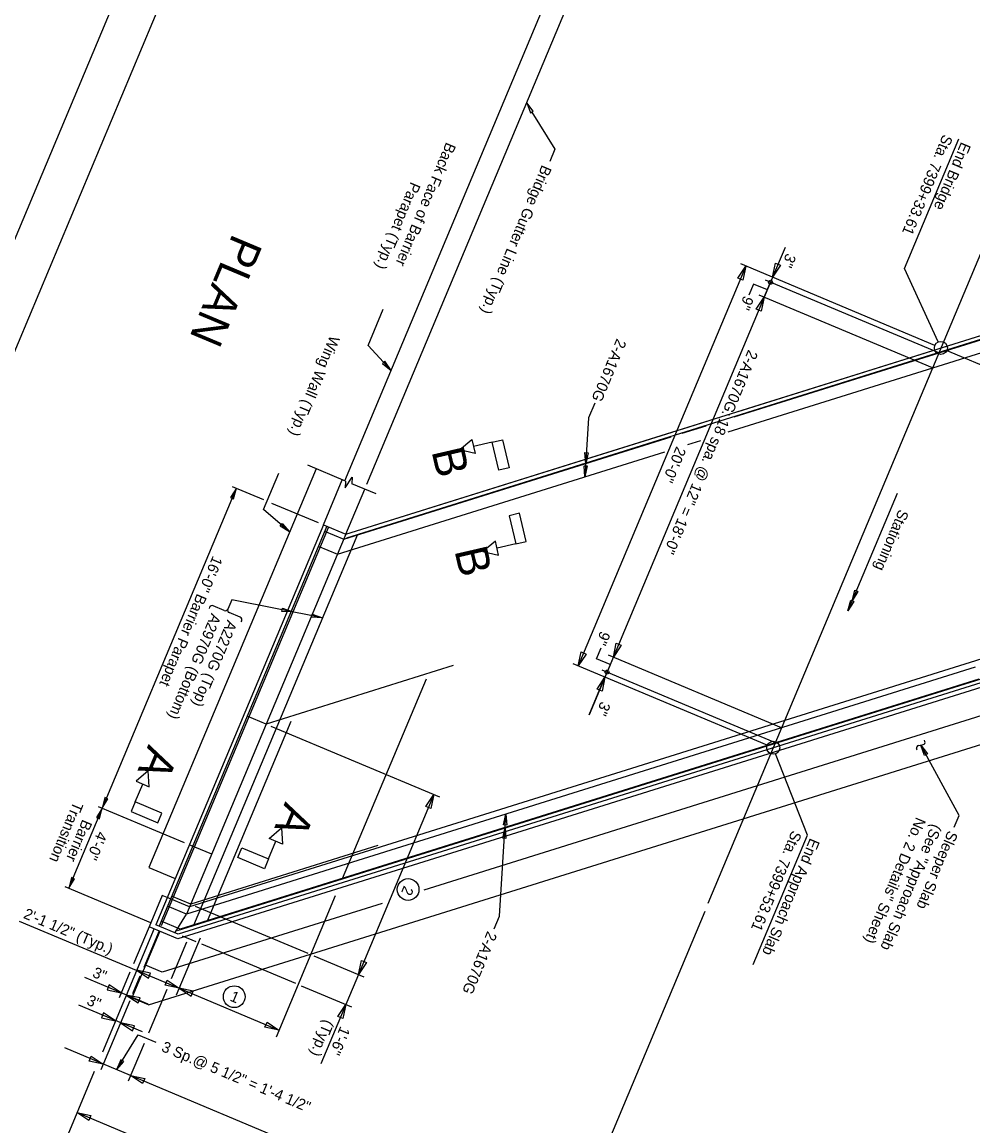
# Model space of a CAD drawing. Extents: x 1968564 to 1968701, y 796599 to 796766.
# Drawn here: x 1968596.6 to 1968640.5, y 796669.3 to 796720.2 of the extents above; entities that cross this region are included whole.
import ezdxf

# ---------------------------------------------------------------- set-up
doc = ezdxf.new("R2010")
doc.units = 0
for name, color, linetype in [('BR_AUTO DIMENSION', 7, 'Continuous'), ('BR_BORDER LINES', 7, 'Continuous'), ('BR_CENTER LINES', 7, 'Continuous'), ('BR_CONCRETE', 7, 'Continuous'), ('BR_DETAILS', 7, 'Continuous'), ('BR_REBAR', 7, 'Continuous'), ('BR_TABLE LINES', 7, 'Continuous'), ('BR_TEXT', 7, 'Continuous'), ('Level 31', 7, 'Continuous')]:
    doc.layers.add(name, color=color, linetype=linetype)

msp = doc.modelspace()

# ---------------------------------------------------------------- linework, layer by layer
at = {"layer": 'BR_AUTO DIMENSION'}
for p, q in [((1968611.464, 796699.011), (1968632.524, 796749.225)), ((1968612.483, 796698.855), (1968633.446, 796748.838)), ((1968612.483, 796698.855), (1968632.89, 796747.51)), ((1968620.099, 796716.016), (1968621.16, 796714.305)), ((1968637.292, 796708.802), (1968639.798, 796714.777)), ((1968621.16, 796714.305), (1968620.923, 796713.741)), ((1968631.786, 796709.774), (1968631.208, 796708.395)), ((1968629.977, 796708.911), (1968622.241, 796690.467)), ((1968638.698, 796705.253), (1968629.746, 796709.008)), ((1968631.388, 796708.825), (1968631.079, 796708.087)), ((1968638.849, 796705.41), (1968637.292, 796708.802)), ((1968630.332, 796708.083), (1968630.116, 796707.569)), ((1968630.965, 796707.817), (1968630.332, 796708.083)), ((1968630.821, 796707.472), (1968631.079, 796708.087)), ((1968631.079, 796708.087), (1968630.821, 796707.472)), ((1968638.877, 796704.907), (1968630.881, 796708.261)), ((1968630.821, 796707.472), (1968622.744, 796688.214)), ((1968638.587, 796704.215), (1968630.59, 796707.569)), ((1968612.539, 796705.251), (1968613.243, 796706.93)), ((1968613.598, 796704.1), (1968612.539, 796705.251)), ((1968639.251, 796705.021), (1968648.6, 796701.1)), ((1968622.999, 796702.586), (1968622.715, 796701.91)), ((1968622.715, 796701.91), (1968622.55, 796699.196)), ((1968607.713, 796697.682), (1968608.417, 796699.36)), ((1968598.724, 796680.219), (1968606.46, 796698.663)), ((1968606.273, 796698.741), (1968607.709, 796698.139)), ((1968636.954, 796698.42), (1968634.687, 796693.016)), ((1968608.917, 796696.657), (1968607.713, 796697.682)), ((1968608.089, 796697.98), (1968610.238, 796697.078)), ((1968605.224, 796693.172), (1968605.202, 796693.12)), ((1968605.9, 796693.024), (1968605.387, 796693.239)), ((1968606.245, 796693.525), (1968606.063, 796693.091)), ((1968610.439, 796692.689), (1968606.245, 796693.525)), ((1968606.642, 796692.713), (1968606.13, 796692.928)), ((1968606.687, 796692.497), (1968606.709, 796692.549)), ((1968623.081, 796690.795), (1968623.296, 796691.308)), ((1968624.009, 796691.231), (1968623.601, 796690.258)), ((1968630.962, 796686.81), (1968622.011, 796690.564)), ((1968623.715, 796690.529), (1968623.081, 796690.795)), ((1968631.625, 796687.616), (1968623.629, 796690.97)), ((1968623.292, 796689.521), (1968623.601, 796690.258)), ((1968631.335, 796686.924), (1968623.338, 796690.278)), ((1968622.744, 796688.214), (1968623.472, 796689.951)), ((1968608.048, 796687.695), (1968615.831, 796684.431)), ((1968632.824, 796682.67), (1968631.349, 796686.415)), ((1968639.812, 796683.57), (1968638.053, 796686.82)), ((1968615.575, 796684.538), (1968612.094, 796676.239)), ((1968600.085, 796683.986), (1968604.049, 796682.324)), ((1968618.61, 796678.928), (1968618.897, 796683.633)), ((1968639.584, 796683.028), (1968639.812, 796683.57)), ((1968630.318, 796676.695), (1968632.824, 796682.67)), ((1968598.538, 796680.298), (1968602.502, 796678.635)), ((1968611.027, 796679.872), (1968608.292, 796673.35)), ((1968604.567, 796679.395), (1968609.763, 796677.216)), ((1968618.363, 796678.339), (1968618.61, 796678.928)), ((1968628.075, 796679.15), (1968621.849, 796664.307)), ((1968596.437, 796678.704), (1968603.817, 796675.609)), ((1968602.663, 796678.352), (1968600.277, 796672.663)), ((1968602.429, 796678.44), (1968601.71, 796676.726)), ((1968602.894, 796678.255), (1968602.184, 796676.562)), ((1968604.786, 796677.919), (1968603.681, 796675.284)), ((1968603.964, 796678.022), (1968604.583, 796677.762)), ((1968604.162, 796677.723), (1968603.457, 796676.043)), ((1968604.849, 796677.651), (1968609.183, 796675.833)), ((1968610.036, 796677.102), (1968612.35, 796676.131)), ((1968601.55, 796676.344), (1968601.054, 796675.161)), ((1968612.094, 796676.239), (1968610.366, 796672.119)), ((1968602.393, 796674.866), (1968599.461, 796676.096)), ((1968602.013, 796676.155), (1968601.671, 796675.34)), ((1968609.456, 796675.718), (1968611.77, 796674.748)), ((1968603.252, 796675.553), (1968602.403, 796673.529)), ((1968603.817, 796675.609), (1968608.428, 796673.675)), ((1968602.127, 796673.586), (1968599.195, 796674.816)), ((1968601.54, 796675.028), (1968600.205, 796671.843)), ((1968600.933, 796671.845), (1968601.931, 796673.452)), ((1968601.931, 796673.452), (1968602.74, 796673.113)), ((1968601.582, 796671.573), (1968598.541, 796672.848)), ((1968602.205, 796673.058), (1968601.473, 796671.311)), ((1968599.902, 796671.768), (1968598.173, 796667.646)), ((1968654.146, 796649.526), (1968601.582, 796671.573)), ((1968620.43, 796660.923), (1968599.105, 796669.867))]:
    msp.add_line(p, q, dxfattribs=at)
for points in [[(1968620.165, 796716.053), (1968619.861, 796716.446), (1968620.036, 796715.981)], [(1968629.61, 796708.36), (1968629.977, 796708.911), (1968629.841, 796708.263)], [(1968631.574, 796708.946), (1968631.208, 796708.395), (1968631.344, 796709.042)], [(1968630.454, 796706.921), (1968630.821, 796707.472), (1968630.685, 796706.825)], [(1968613.204, 796704.417), (1968613.598, 796704.1), (1968613.315, 796704.519)], [(1968622.693, 796700.303), (1968622.587, 796699.809), (1968622.543, 796700.312)], [(1968622.655, 796699.691), (1968622.55, 796699.196), (1968622.506, 796699.7)], [(1968606.335, 796698.173), (1968606.46, 796698.663), (1968606.197, 796698.231)], [(1968608.577, 796697.031), (1968608.917, 796696.657), (1968608.483, 796696.914)], [(1968635.143, 796693.908), (1968634.88, 796693.476), (1968635.005, 796693.966)], [(1968608.587, 796693.134), (1968609.063, 796692.963), (1968608.558, 796692.987)], [(1968634.95, 796693.448), (1968634.687, 796693.016), (1968634.812, 796693.506)], [(1968609.963, 796692.86), (1968610.439, 796692.689), (1968609.934, 796692.713)], [(1968624.226, 796691.424), (1968623.859, 796690.873), (1968623.995, 796691.521)], [(1968622.608, 796691.018), (1968622.241, 796690.467), (1968622.377, 796691.115)], [(1968623.106, 796689.4), (1968623.472, 796689.951), (1968623.336, 796689.303)], [(1968638.225, 796686.345), (1968638.053, 796686.82), (1968638.357, 796686.416)], [(1968600.395, 796684.398), (1968600.271, 796683.908), (1968600.534, 796684.34)], [(1968615.208, 796683.987), (1968615.575, 796684.538), (1968615.439, 796683.89)], [(1968600.147, 796683.418), (1968600.271, 796683.908), (1968600.009, 796683.476)], [(1968618.792, 796683.138), (1968618.897, 796683.633), (1968618.941, 796683.129)], [(1968618.754, 796682.525), (1968618.86, 796683.02), (1968618.904, 796682.516)], [(1968598.848, 796680.71), (1968598.724, 796680.219), (1968598.987, 796680.652)], [(1968612.46, 796676.79), (1968612.094, 796676.239), (1968612.23, 796676.886)], [(1968602.505, 796676.294), (1968601.858, 796676.431), (1968602.409, 796676.064)], [(1968600.501, 796675.524), (1968601.149, 796675.388), (1968600.598, 796675.755)], [(1968603.266, 796675.975), (1968603.817, 796675.609), (1968603.169, 796675.745)], [(1968602.027, 796675.155), (1968601.38, 796675.291), (1968601.931, 796674.925)], [(1968604.465, 796675.472), (1968603.817, 796675.609), (1968604.368, 796675.242)], [(1968611.147, 796674.304), (1968611.514, 796674.855), (1968611.378, 796674.208)], [(1968600.235, 796674.244), (1968600.883, 796674.108), (1968600.332, 796674.474)], [(1968601.762, 796673.875), (1968601.114, 796674.011), (1968601.665, 796673.644)], [(1968607.877, 796674.041), (1968608.428, 796673.675), (1968607.78, 796673.811)], [(1968599.763, 796672.471), (1968600.314, 796672.104), (1968599.666, 796672.24)], [(1968601.133, 796672.309), (1968600.933, 796671.845), (1968601.26, 796672.23)], [(1968602.133, 796671.206), (1968601.582, 796671.573), (1968602.23, 796671.436)], [(1968599.656, 796669.5), (1968599.105, 796669.867), (1968599.752, 796669.731)]]:
    msp.add_lwpolyline(points, close=True, dxfattribs=at)
for centre, radius in [((1968631.111, 796708.164), 0.0915), ((1968638.974, 796705.137), 0.3), ((1968623.569, 796690.182), 0.0915), ((1968631.239, 796686.694), 0.3), ((1968614.386, 796680.157), 0.502), ((1968606.363, 796675.215), 0.502)]:
    msp.add_circle(centre, radius, dxfattribs=at)
for centre, start, end in [((1968605.339, 796693.124), 67.246, 157.246), ((1968605.948, 796693.14), 247.246, 337.246), ((1968606.178, 796693.043), 157.246, 247.246), ((1968606.594, 796692.598), 337.246, 67.246)]:
    msp.add_arc(centre, 0.125, start, end, dxfattribs=at)
at = {"layer": 'BR_BORDER LINES'}
msp.add_line((1968618.549, 796758.212), (1968566.464, 796634.028), dxfattribs=at)
at = {"layer": 'BR_CENTER LINES'}
msp.add_line((1968651.27, 796734.454), (1968628.225, 796679.508), dxfattribs=at)
at = {"layer": 'BR_CONCRETE'}
for p, q in [((1968629.619, 796702.21), (1968683.91, 796719.2)), ((1968627.062, 796701.409), (1968628.277, 796701.79)), ((1968611.513, 796696.543), (1968626.579, 796701.258)), ((1968670.61, 796700.106), (1968604.305, 796679.356)), ((1968610.138, 796699.567), (1968602.421, 796681.168)), ((1968670.547, 796698.777), (1968603.767, 796677.878)), ((1968670.558, 796698.998), (1968603.778, 796678.1)), ((1968610.476, 796696.979), (1968611.348, 796699.059)), ((1968611.513, 796696.543), (1968612.386, 796698.624)), ((1968669.976, 796697.288), (1968615.12, 796680.121)), ((1968610.476, 796696.979), (1968602.74, 796678.535)), ((1968610.476, 796696.979), (1968611.513, 796696.543)), ((1968611.513, 796696.543), (1968604.164, 796679.022)), ((1968602.408, 796674.833), (1968669.344, 796695.781)), ((1968605.325, 796681.789), (1968604.287, 796682.224)), ((1968602.421, 796681.168), (1968603.632, 796680.661)), ((1968603.037, 796679.888), (1968602.429, 796678.44)), ((1968603.267, 796679.791), (1968603.037, 796679.888)), ((1968604.305, 796679.356), (1968603.267, 796679.791)), ((1968613.192, 796679.518), (1968603.04, 796676.341)), ((1968603.629, 796678.169), (1968604.164, 796679.022)), ((1968603.767, 796677.878), (1968602.429, 796678.44)), ((1968603.778, 796678.1), (1968602.74, 796678.535)), ((1968602.929, 796678.23), (1968601.639, 796675.156)), ((1968603.04, 796676.341), (1968602.271, 796676.663)), ((1968602.408, 796674.833), (1968601.639, 796675.156))]:
    msp.add_line(p, q, dxfattribs=at)
at = {"layer": 'BR_DETAILS'}
for p, q in [((1968611.495, 796698.998), (1968609.765, 796699.723)), ((1968612.909, 796698.405), (1968611.795, 796698.872)), ((1968638.236, 796686.984), (1968638.215, 796687.049)), ((1968637.873, 796686.59), (1968637.855, 796686.638)), ((1968637.953, 796686.801), (1968638.154, 796686.839))]:
    msp.add_line(p, q, dxfattribs=at)
msp.add_lwpolyline([(1968611.495, 796698.998), (1968611.483, 796698.689), (1968611.807, 796699.181), (1968611.795, 796698.872)], dxfattribs=at)
for centre, radius, start, end in [((1968638.143, 796686.941), 0.103, 276.7713, 25.0569), ((1968637.961, 796686.686), 0.116, 94.3265, 204.1253)]:
    msp.add_arc(centre, radius, start, end, dxfattribs=at)
at = {"layer": 'BR_REBAR'}
for p, q in [((1968629.434, 796701.951), (1968647.133, 796707.49)), ((1968629.151, 796701.262), (1968647.305, 796706.943)), ((1968627.027, 796701.198), (1968628.135, 796701.545)), ((1968611.416, 796696.313), (1968626.532, 796701.043)), ((1968627.298, 796700.682), (1968627.898, 796700.87)), ((1968611.126, 796695.621), (1968626.227, 796700.347)), ((1968610.69, 796696.843), (1968602.987, 796678.477)), ((1968610.533, 796696.684), (1968611.416, 796696.313)), ((1968612.053, 796696.538), (1968604.486, 796678.496)), ((1968610.243, 796695.992), (1968611.126, 796695.621)), ((1968616.468, 796690.483), (1968607.839, 796687.783)), ((1968640.552, 796690.409), (1968604.164, 796679.022)), ((1968640.723, 796689.862), (1968603.874, 796678.33)), ((1968615.219, 796689.866), (1968611.351, 796680.645)), ((1968607.839, 796687.783), (1968606.955, 796688.153)), ((1968608.978, 796687.913), (1968605.11, 796678.692)), ((1968612.987, 796682.184), (1968604.358, 796679.483)), ((1968604.358, 796679.483), (1968603.474, 796679.854)), ((1968604.164, 796679.022), (1968603.281, 796679.393)), ((1968603.874, 796678.33), (1968602.991, 796678.701))]:
    msp.add_line(p, q, dxfattribs=at)
at = {"layer": 'BR_TABLE LINES'}
for p, q in [((1968618.271, 796700.792), (1968617.405, 796700.592)), ((1968619.356, 796696.099), (1968618.49, 796695.899)), ((1968601.793, 796684.199), (1968602.137, 796685.018)), ((1968607.943, 796681.565), (1968608.287, 796682.384))]:
    msp.add_line(p, q, dxfattribs=at)
for points in [[(1968617.48, 796700.267), (1968616.755, 796700.442), (1968617.33, 796700.916)], [(1968619.048, 796699.603), (1968618.571, 796699.493), (1968618.271, 796700.792), (1968618.747, 796700.902)], [(1968619.532, 796697.508), (1968619.056, 796697.398), (1968619.356, 796696.099), (1968619.832, 796696.209)], [(1968618.415, 796696.224), (1968617.841, 796695.749), (1968618.565, 796695.574)], [(1968602.444, 796684.889), (1968602.395, 796685.633), (1968601.829, 796685.147)], [(1968602.834, 796683.232), (1968603.023, 796683.683), (1968601.793, 796684.199), (1968601.604, 796683.748)], [(1968607.979, 796682.513), (1968608.545, 796682.999), (1968608.594, 796682.255)], [(1968606.524, 796681.629), (1968606.713, 796682.08), (1968607.943, 796681.565), (1968607.754, 796681.114)]]:
    msp.add_lwpolyline(points, close=True, dxfattribs=at)
at = {"layer": 'Level 31'}
for p, q in [((1968611.513, 796696.543), (1968683.91, 796719.2)), ((1968611.563, 796696.384), (1968671.575, 796715.165)), ((1968670.508, 796699.157), (1968603.728, 796678.259)), ((1968610.629, 796696.914), (1968602.894, 796678.471))]:
    msp.add_line(p, q, dxfattribs=at)
msp.add_lwpolyline([(1968619.541, 796765.748), (1968563.846, 796632.955), (1968644.997, 796598.919), (1968700.693, 796731.712)], close=True, dxfattribs=at)

# ---------------------------------------------------------------- texts
at = {"layer": 'BR_AUTO DIMENSION'}
for s, height, rotation, p in [('3"', 0.5, 247.246, (1968631.851, 796709.533)), ('9"', 0.5, 247.246, (1968629.891, 796707.579)), ('2-A1670G: 18 spa. @ 12" = 18\'-0"', 0.5, 247.246, (1968630.089, 796705.08)), ('20\'-0"', 0.5, 247.246, (1968626.773, 796700.626)), ('16\'-0" Barrier Parapet', 0.5, 247.246, (1968605.382, 796695.576)), ('9"', 0.5, 247.246, (1968623.274, 796692.113)), ('3"', 0.5, 247.246, (1968623.288, 796688.864)), ('4\'-0"', 0.5, 247.246, (1968600.057, 796682.878)), ('2', 0.5, 247.246, (1968614.2, 796680.361)), ('2\'-1 1/2" (Typ.)', 0.5, 337.246, (1968596.598, 796678.855)), ('3"', 0.5, 337.246, (1968599.781, 796676.143)), ('3"', 0.5, 337.246, (1968599.515, 796674.862)), ('1', 0.5, 337.246, (1968606.126, 796675.044)), ('3 Sp.@ 5 1/2" = 1\'-4 1/2"', 0.49995, 337.246, (1968602.966, 796672.716))]:
    msp.add_text(s, height=height, rotation=rotation, dxfattribs=at).set_placement(p)
at = {"layer": 'BR_TEXT'}
for s, height, rotation, p in [('Sta. 7399+33.61', 0.49995, 247.246, (1968639.079, 796715.015)), ('Back Face of Barrier', 0.49995, 247.246, (1968616.15, 796714.652)), ('End Bridge', 0.4999, 247.246, (1968639.915, 796714.664)), ('Bridge Gutter Line (Typ.)', 0.49995, 247.246, (1968620.568, 796713.606)), ('Parapet (Typ.)', 0.49995, 247.246, (1968614.516, 796712.824)), ('PLAN', 1.5, 247.246, (1968606.308, 796710.459)), ('Wing Wall (Typ.)', 0.49995, 247.246, (1968610.788, 796705.744)), ('2-A1670G', 0.4999, 247.246, (1968624.019, 796705.596)), ('B', 1.5, 283.0193, (1968615.461, 796700.376)), ('Stationing', 0.4999, 247.246, (1968637.047, 796697.724)), ('B', 1.5, 283.0193, (1968616.52, 796695.794)), ('A2970G (Bottom) ', 0.49995, 247.246, (1968605.309, 796692.927)), ('A2270G (Top)', 0.49995, 247.246, (1968606.047, 796692.617)), ('A', 1.5, 247.246, (1968602.41, 796686.876)), ('Transition', 0.4999, 247.246, (1968598.95, 796684.244)), ('A', 1.5, 247.246, (1968608.721, 796684.229)), ('Barrier', 0.4999, 247.246, (1968599.364, 796683.42)), ('No. 2 Details" Sheet)', 0.49995, 247.246, (1968637.838, 796683.526)), ('Sta. 7399+53.61', 0.49995, 247.246, (1968632.105, 796682.908)), ('(See "Approach Slab', 0.49995, 247.246, (1968638.576, 796683.216)), ('Sleeper Slab ', 0.49995, 247.246, (1968639.314, 796682.907)), ('End Approach Slab', 0.49995, 247.246, (1968632.941, 796682.558)), ('2-A1670G', 0.4999, 247.246, (1968618.05, 796678.264)), ('(Typ.)', 0.4999, 247.246, (1968610.531, 796674.19)), ('1\'-6"', 0.4999, 247.246, (1968611.269, 796673.881))]:
    msp.add_text(s, height=height, rotation=rotation, dxfattribs=at).set_placement(p)

doc.saveas('drawing.dxf')
